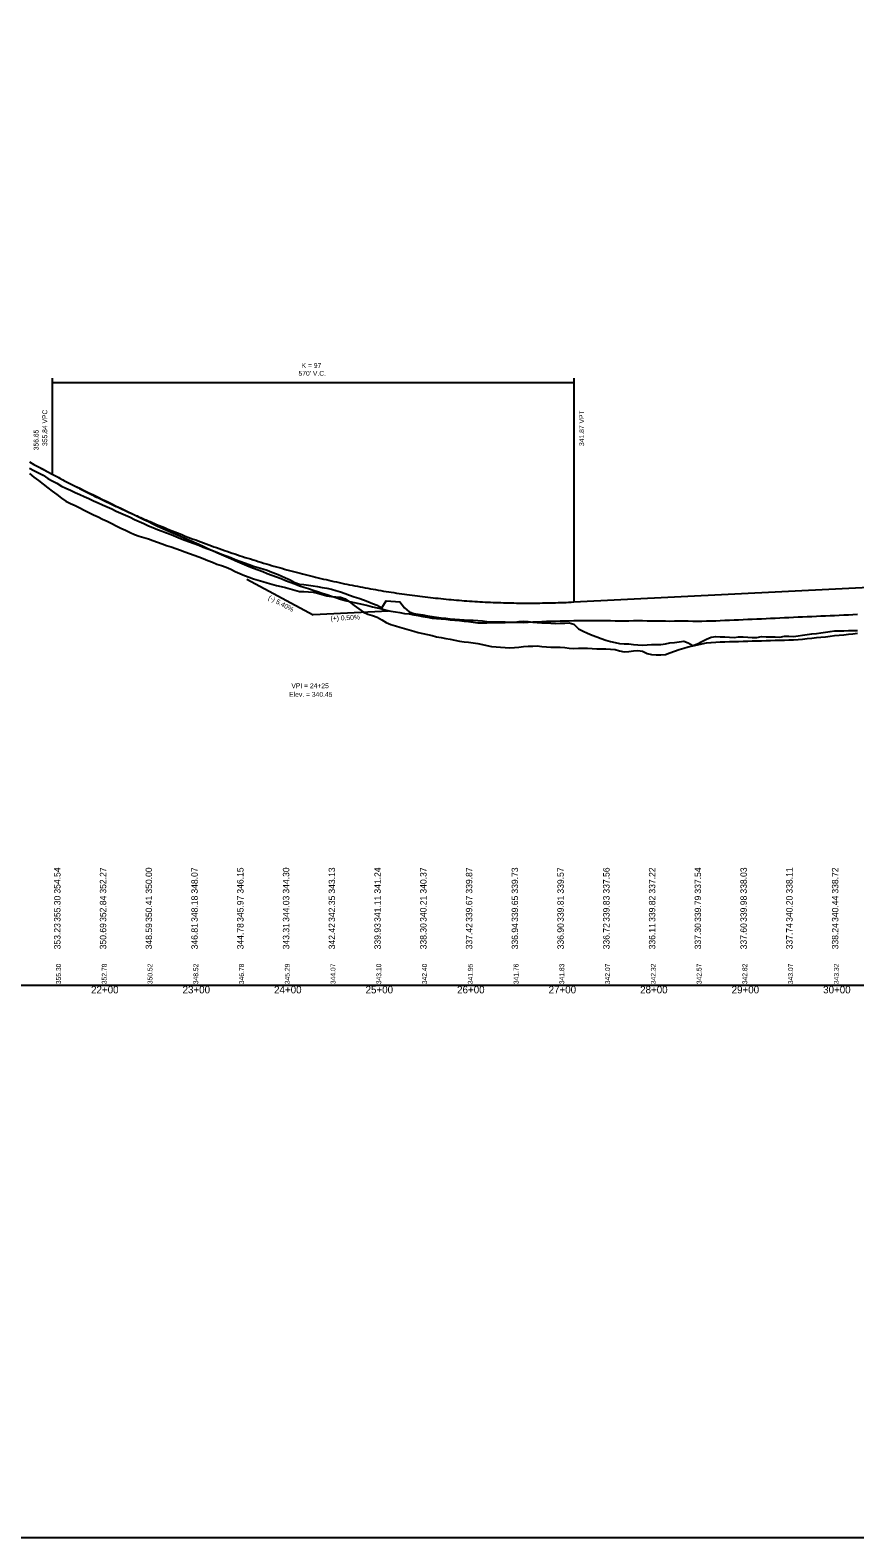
# Model space of a CAD drawing. Extents: x 2005261 to 2010661, y 1001568 to 1006764.
# Drawn here: x 2006738 to 2007639, y 1003464 to 1005112 of the extents above; entities that cross this region are included whole.
import ezdxf

# ---------------------------------------------------------------- set-up
doc = ezdxf.new("R2010")
doc.units = 0
for name, color, linetype in [('RD_DDB_GradeTX', 7, 'Continuous'), ('RD_DDB_Profile_EX', 7, 'Continuous'), ('RD_DDB_Profile_Lbl', 7, 'Continuous'), ('RD_DDB_Profile_PR', 7, 'Continuous'), ('RD_DDB_StaTX', 7, 'Continuous'), ('RD_DDB_StripGrade', 7, 'Continuous'), ('RD_DDB_VCLbl', 7, 'Continuous'), ('RD_GPK_Profile_Cell', 7, 'Continuous'), ('RD_Sketch2', 7, 'Continuous'), ('RD_Sketch3', 7, 'Continuous'), ('RD_Sketch4', 7, 'Continuous')]:
    doc.layers.add(name, color=color, linetype=linetype)

msp = doc.modelspace()

# ---------------------------------------------------------------- linework, layer by layer
at = {"layer": 'RD_DDB_GradeTX'}
for p in [(2006974.2, 1004512), (2007129, 1004477)]:
    msp.add_line(p, (2007046.7, 1004472.9), dxfattribs=at)
at = {"layer": 'RD_DDB_Profile_EX'}
for points in [[(2006736.7, 1004640.2), (2006741.7, 1004637.5), (2006746.7, 1004634.8), (2006751.7, 1004632.2), (2006756.7, 1004629.5), (2006761.7, 1004626.8), (2006766.7, 1004624.1), (2006771.7, 1004621.4), (2006776.7, 1004618.7), (2006781.7, 1004616.2), (2006786.7, 1004613.8), (2006791.7, 1004611.4), (2006796.7, 1004608.9), (2006801.7, 1004606.5), (2006806.7, 1004604.1), (2006811.7, 1004601.7), (2006816.7, 1004599.2), (2006821.7, 1004596.8), (2006826.7, 1004594.4), (2006831.7, 1004592), (2006836.7, 1004589.5), (2006841.7, 1004587.1), (2006846.7, 1004584.7), (2006851.7, 1004582.2), (2006856.7, 1004579.8), (2006861.7, 1004577.4), (2006866.7, 1004575), (2006871.7, 1004572.5), (2006876.7, 1004570.1), (2006881.7, 1004567.9), (2006886.7, 1004565.7), (2006891.7, 1004563.5), (2006896.7, 1004561.2), (2006901.7, 1004559), (2006906.7, 1004556.8), (2006911.7, 1004554.6), (2006916.7, 1004552.4), (2006921.7, 1004550.2), (2006926.7, 1004548), (2006931.7, 1004545.7), (2006936.7, 1004543.5), (2006941.7, 1004541.3), (2006946.7, 1004539.1), (2006951.7, 1004536.9), (2006956.7, 1004534.7), (2006961.7, 1004532.5), (2006966.7, 1004530.3), (2006971.7, 1004528.1), (2006976.7, 1004525.9), (2006981.7, 1004524.1), (2006986.7, 1004522.2), (2006991.7, 1004520.3), (2006996.7, 1004518.4), (2007001.7, 1004516.5), (2007006.7, 1004514.5), (2007011.7, 1004512.6), (2007016.7, 1004510.7), (2007021.7, 1004508.7), (2007026.7, 1004506.8), (2007031.7, 1004504.9), (2007036.7, 1004503.4), (2007041.7, 1004501.8), (2007046.7, 1004500.2), (2007051.7, 1004498.6), (2007056.7, 1004496.9), (2007061.7, 1004495.3), (2007066.7, 1004493.6), (2007071.7, 1004491.9), (2007076.7, 1004490.1), (2007081.7, 1004488.8), (2007086.7, 1004487.7), (2007091.7, 1004486.6), (2007096.7, 1004485.5), (2007101.7, 1004484.3), (2007106.7, 1004483.1), (2007111.7, 1004481.9), (2007116.7, 1004480.7), (2007121.7, 1004479.5), (2007126.7, 1004478.2), (2007131.7, 1004476.9), (2007136.7, 1004476.2), (2007141.7, 1004475.5), (2007146.7, 1004474.7), (2007151.7, 1004474), (2007156.7, 1004473.1), (2007161.7, 1004472.3), (2007166.7, 1004471.4), (2007171.7, 1004470.5), (2007176.7, 1004469.6)], [(2007176.7, 1004469.6), (2007181.7, 1004468.9), (2007186.7, 1004468.6), (2007191.7, 1004468.2), (2007196.7, 1004467.7), (2007201.7, 1004467.3), (2007206.7, 1004466.8), (2007211.7, 1004466.2), (2007216.7, 1004465.7), (2007221.7, 1004465.1), (2007226.7, 1004464.5), (2007231.7, 1004464.2), (2007236.7, 1004464.4), (2007241.7, 1004464.6), (2007246.7, 1004464.7), (2007251.7, 1004464.8), (2007256.7, 1004464.8), (2007261.7, 1004464.9), (2007266.7, 1004464.9), (2007271.7, 1004464.9), (2007276.7, 1004464.8), (2007281.7, 1004465), (2007286.7, 1004465.3), (2007291.7, 1004465.5), (2007296.7, 1004465.8), (2007301.7, 1004466), (2007306.7, 1004466.1), (2007311.7, 1004466.3), (2007316.7, 1004466.4), (2007321.7, 1004466.5), (2007326.7, 1004466.6), (2007331.7, 1004466.7), (2007336.7, 1004466.7), (2007341.7, 1004466.8), (2007346.7, 1004466.9), (2007351.7, 1004466.9), (2007356.7, 1004466.9), (2007361.7, 1004466.8), (2007366.7, 1004466.7), (2007371.7, 1004466.7), (2007376.7, 1004466.6), (2007381.7, 1004466.5), (2007386.7, 1004466.4), (2007391.7, 1004466.6), (2007396.7, 1004466.7), (2007401.7, 1004466.8), (2007406.7, 1004466.7), (2007411.7, 1004466.5), (2007416.7, 1004466.5), (2007421.7, 1004466.6), (2007426.7, 1004466.6), (2007431.7, 1004466.5), (2007436.7, 1004466.3), (2007441.7, 1004466.4), (2007446.7, 1004466.5), (2007451.7, 1004466.5), (2007456.7, 1004466.5), (2007461.7, 1004466.3), (2007466.7, 1004466.3), (2007471.7, 1004466.3), (2007476.7, 1004466.4), (2007481.7, 1004466.4), (2007486.7, 1004466.6), (2007491.7, 1004466.9), (2007496.7, 1004467.1), (2007501.7, 1004467.3), (2007506.7, 1004467.5), (2007511.7, 1004467.7), (2007516.7, 1004467.9), (2007521.7, 1004468.2), (2007526.7, 1004468.4), (2007531.7, 1004468.6), (2007536.7, 1004468.8), (2007541.7, 1004469.1), (2007546.7, 1004469.3), (2007551.7, 1004469.5), (2007556.7, 1004469.7), (2007561.7, 1004470), (2007566.7, 1004470.2), (2007571.7, 1004470.4), (2007576.7, 1004470.7), (2007581.7, 1004470.9), (2007586.7, 1004471.1), (2007591.7, 1004471.3), (2007596.7, 1004471.6), (2007601.7, 1004471.8), (2007606.7, 1004472), (2007611.7, 1004472.3), (2007616.7, 1004472.5), (2007621.7, 1004472.8), (2007626.7, 1004473), (2007631.7, 1004473.2), (2007636.7, 1004473.5), (2007641.7, 1004473.7)]]:
    msp.add_lwpolyline(points, dxfattribs=at)
at = {"layer": 'RD_DDB_Profile_PR'}
for p, q in [((2006746.7, 1004634.9), (2006761.7, 1004626.8)), ((2007331.7, 1004487.1), (2007916.7, 1004516.4))]:
    msp.add_line(p, q, dxfattribs=at)
msp.add_spline([(2006761.7, 1004626.8), (2006773.1, 1004620.7), (2006784.5, 1004614.7), (2006795.9, 1004608.9), (2006807.3, 1004603.2), (2006818.7, 1004597.7), (2006830.1, 1004592.3), (2006841.5, 1004587), (2006852.9, 1004581.8), (2006864.3, 1004576.8), (2006875.7, 1004571.9), (2006887.1, 1004567.2), (2006898.5, 1004562.6), (2006909.9, 1004558.1), (2006921.3, 1004553.8), (2006932.7, 1004549.6), (2006944.1, 1004545.5), (2006955.5, 1004541.5), (2006966.9, 1004537.7), (2006978.3, 1004534.1), (2006989.7, 1004530.5), (2007001.1, 1004527.1), (2007012.5, 1004523.9), (2007023.9, 1004520.7), (2007035.3, 1004517.8), (2007046.7, 1004514.9), (2007058.1, 1004512.2), (2007069.5, 1004509.6), (2007080.9, 1004507.1), (2007092.3, 1004504.8), (2007103.7, 1004502.6), (2007115.1, 1004500.6), (2007126.5, 1004498.6), (2007137.9, 1004496.9), (2007149.3, 1004495.2), (2007160.7, 1004493.7), (2007172.1, 1004492.3), (2007183.5, 1004491.1), (2007194.9, 1004489.9), (2007206.3, 1004489), (2007217.7, 1004488.1), (2007229.1, 1004487.4), (2007240.5, 1004486.8), (2007251.9, 1004486.4), (2007263.3, 1004486.1), (2007274.7, 1004485.9), (2007286.1, 1004485.9), (2007297.5, 1004486), (2007308.9, 1004486.2), (2007320.3, 1004486.6), (2007331.7, 1004487.1)], degree=3, dxfattribs=at)
at = {"layer": 'RD_DDB_VCLbl'}
for p, q in [((2006761.7, 1004731.8), (2006761.7, 1004626.8)), ((2006761.7, 1004726.8), (2007331.7, 1004726.8)), ((2007331.7, 1004731.8), (2007331.7, 1004487.1))]:
    msp.add_line(p, q, dxfattribs=at)
at = {"layer": 'RD_GPK_Profile_Cell'}
msp.add_line((2006171.7, 1004068.4), (2009471.7, 1004068.4), dxfattribs=at)
at = {"layer": 'RD_Sketch2'}
for points in [[(2006736.7, 1004627.5), (2006741.7, 1004623.6), (2006746.7, 1004619.7), (2006751.7, 1004615.8), (2006756.7, 1004611.9), (2006761.7, 1004608.3), (2006766.7, 1004604.6), (2006771.7, 1004600.7), (2006776.7, 1004597.3), (2006781.7, 1004594.9), (2006786.7, 1004592.4), (2006791.7, 1004590), (2006796.7, 1004587.5), (2006801.7, 1004585), (2006806.7, 1004582.5), (2006811.7, 1004580.1), (2006816.7, 1004577.7), (2006821.7, 1004575.3), (2006826.7, 1004572.8), (2006831.7, 1004570.4), (2006836.7, 1004567.9), (2006841.7, 1004565.5), (2006846.7, 1004563.1), (2006851.7, 1004560.8), (2006856.7, 1004559.2), (2006861.7, 1004557.6), (2006866.7, 1004556), (2006871.7, 1004554.3), (2006876.7, 1004552.5), (2006881.7, 1004550.7), (2006886.7, 1004549), (2006891.7, 1004547.2), (2006896.7, 1004545.5), (2006901.7, 1004543.8), (2006906.7, 1004541.8), (2006911.7, 1004540), (2006916.7, 1004538.2), (2006921.7, 1004536.5), (2006926.7, 1004534.7), (2006931.7, 1004532.6), (2006936.7, 1004530.5), (2006941.7, 1004528.6), (2006946.7, 1004526.8), (2006951.7, 1004525), (2006956.7, 1004522.8), (2006961.7, 1004520.6), (2006966.7, 1004518.4), (2006971.7, 1004516.2), (2006976.7, 1004514.3), (2006981.7, 1004512.4), (2006986.7, 1004511), (2006991.7, 1004509.5), (2006996.7, 1004508.1), (2007001.7, 1004506.6), (2007006.7, 1004505.2), (2007011.7, 1004504.1), (2007016.7, 1004503), (2007021.7, 1004501.5), (2007026.7, 1004499.9), (2007031.7, 1004498.5), (2007036.7, 1004498.4), (2007041.7, 1004498.3), (2007046.7, 1004497.7), (2007051.7, 1004496.9), (2007056.7, 1004495.3), (2007061.7, 1004493.9), (2007066.7, 1004493.2), (2007071.7, 1004492.6), (2007076.7, 1004492.2), (2007081.7, 1004490.4), (2007086.7, 1004487.1), (2007091.7, 1004483.3), (2007096.7, 1004479.6), (2007101.7, 1004476), (2007106.7, 1004473.7), (2007111.7, 1004472.3), (2007116.7, 1004470.6), (2007121.7, 1004467.7), (2007126.7, 1004464.8), (2007131.7, 1004462.6), (2007136.7, 1004461), (2007141.7, 1004459.5), (2007146.7, 1004458), (2007151.7, 1004456.5), (2007156.7, 1004455.1), (2007161.7, 1004453.9), (2007166.7, 1004452.7), (2007171.7, 1004451.4), (2007176.7, 1004450.3)], [(2007176.7, 1004450.3), (2007181.7, 1004449.2), (2007186.7, 1004448.2), (2007191.7, 1004447.3), (2007196.7, 1004446.4), (2007201.7, 1004445.4), (2007206.7, 1004444.4), (2007211.7, 1004443.7), (2007216.7, 1004443.1), (2007221.7, 1004442.6), (2007226.7, 1004441.7), (2007231.7, 1004440.6), (2007236.7, 1004439.6), (2007241.7, 1004438.5), (2007246.7, 1004438.1), (2007251.7, 1004437.8), (2007256.7, 1004437.5), (2007261.7, 1004437.1), (2007266.7, 1004437.2), (2007271.7, 1004437.8), (2007276.7, 1004438.4), (2007281.7, 1004438.8), (2007286.7, 1004438.9), (2007291.7, 1004439.1), (2007296.7, 1004438.6), (2007301.7, 1004438.1), (2007306.7, 1004437.8), (2007311.7, 1004437.8), (2007316.7, 1004437.8), (2007321.7, 1004437.4), (2007326.7, 1004436.7), (2007331.7, 1004436.4), (2007336.7, 1004436.6), (2007341.7, 1004436.8), (2007346.7, 1004436.7), (2007351.7, 1004436.3), (2007356.7, 1004436), (2007361.7, 1004435.9), (2007366.7, 1004435.8), (2007371.7, 1004435.6), (2007376.7, 1004435), (2007381.7, 1004433.9), (2007386.7, 1004432.5), (2007391.7, 1004433.1), (2007396.7, 1004433.6), (2007401.7, 1004434), (2007406.7, 1004433.3), (2007411.7, 1004430.9), (2007416.7, 1004429.6), (2007421.7, 1004429.5), (2007426.7, 1004429.2), (2007431.7, 1004429.8), (2007436.7, 1004431.7), (2007441.7, 1004433.5), (2007446.7, 1004435.1), (2007451.7, 1004436.7), (2007456.7, 1004438.1), (2007461.7, 1004439.3), (2007466.7, 1004440.4), (2007471.7, 1004441.4), (2007476.7, 1004442.3), (2007481.7, 1004443), (2007486.7, 1004443.2), (2007491.7, 1004443.4), (2007496.7, 1004443.6), (2007501.7, 1004443.8), (2007506.7, 1004443.8), (2007511.7, 1004444), (2007516.7, 1004444.2), (2007521.7, 1004444.4), (2007526.7, 1004444.6), (2007531.7, 1004444.6), (2007536.7, 1004444.8), (2007541.7, 1004445), (2007546.7, 1004445.1), (2007551.7, 1004445.3), (2007556.7, 1004445.3), (2007561.7, 1004445.5), (2007566.7, 1004445.7), (2007571.7, 1004445.8), (2007576.7, 1004446.1), (2007581.7, 1004446.6), (2007586.7, 1004447.2), (2007591.7, 1004447.7), (2007596.7, 1004448.3), (2007601.7, 1004448.6), (2007606.7, 1004449.2), (2007611.7, 1004449.7), (2007616.7, 1004450.3), (2007621.7, 1004450.8), (2007626.7, 1004451.2), (2007631.7, 1004451.8), (2007636.7, 1004452.4), (2007641.7, 1004453)]]:
    msp.add_lwpolyline(points, dxfattribs=at)
at = {"layer": 'RD_Sketch3'}
for points in [[(2006736.7, 1004633.2), (2006741.7, 1004630.7), (2006746.7, 1004628.1), (2006751.7, 1004625.6), (2006756.7, 1004622.1), (2006761.7, 1004619.5), (2006766.7, 1004617), (2006771.7, 1004613.8), (2006776.7, 1004611.5), (2006781.7, 1004609.2), (2006786.7, 1004606.9), (2006791.7, 1004604.6), (2006796.7, 1004602.5), (2006801.7, 1004600.1), (2006806.7, 1004597.8), (2006811.7, 1004595.5), (2006816.7, 1004593.2), (2006821.7, 1004591.1), (2006826.7, 1004588.8), (2006831.7, 1004586.5), (2006836.7, 1004584.2), (2006841.7, 1004581.9), (2006846.7, 1004579.8), (2006851.7, 1004577.4), (2006856.7, 1004575.1), (2006861.7, 1004572.8), (2006866.7, 1004570.5), (2006871.7, 1004568.4), (2006876.7, 1004566.4), (2006881.7, 1004564.5), (2006886.7, 1004562.7), (2006891.7, 1004560.8), (2006896.7, 1004558.8), (2006901.7, 1004556.6), (2006906.7, 1004554.8), (2006911.7, 1004552.9), (2006916.7, 1004551), (2006921.7, 1004549.1), (2006926.7, 1004547), (2006931.7, 1004545.1), (2006936.7, 1004543.3), (2006941.7, 1004541.4), (2006946.7, 1004539.5), (2006951.7, 1004537.4), (2006956.7, 1004535.6), (2006961.7, 1004533.7), (2006966.7, 1004531.8), (2006971.7, 1004529.9), (2006976.7, 1004527.9), (2006981.7, 1004526.4), (2006986.7, 1004524.9), (2006991.7, 1004523.4), (2006996.7, 1004521.8), (2007001.7, 1004519.6), (2007006.7, 1004517.7), (2007011.7, 1004515.7), (2007016.7, 1004513.6), (2007021.7, 1004511.4), (2007026.7, 1004508.4), (2007031.7, 1004506.7), (2007036.7, 1004506.2), (2007041.7, 1004505.6), (2007046.7, 1004504.8), (2007051.7, 1004504), (2007056.7, 1004503.1), (2007061.7, 1004502.2), (2007066.7, 1004501), (2007071.7, 1004499.7), (2007076.7, 1004498.3), (2007081.7, 1004496.4), (2007086.7, 1004494.4), (2007091.7, 1004492.8), (2007096.7, 1004491.2), (2007101.7, 1004489.4), (2007106.7, 1004487.5), (2007111.7, 1004485.6), (2007116.7, 1004483.5), (2007121.7, 1004480.8), (2007126.7, 1004488.5), (2007131.7, 1004488), (2007136.7, 1004487.5), (2007141.7, 1004487.1), (2007146.7, 1004480.7), (2007151.7, 1004476.5), (2007156.7, 1004474.6), (2007161.7, 1004473.7), (2007166.7, 1004472.9), (2007171.7, 1004472.1), (2007176.7, 1004471.1)], [(2007176.7, 1004471.1), (2007181.7, 1004470.4), (2007186.7, 1004469.8), (2007191.7, 1004469.3), (2007196.7, 1004468.8), (2007201.7, 1004468.3), (2007206.7, 1004467.9), (2007211.7, 1004467.6), (2007216.7, 1004467.3), (2007221.7, 1004467.1), (2007226.7, 1004466.9), (2007231.7, 1004466.4), (2007236.7, 1004465.8), (2007241.7, 1004465.3), (2007246.7, 1004465.3), (2007251.7, 1004465.5), (2007256.7, 1004465.3), (2007261.7, 1004465.1), (2007266.7, 1004465.1), (2007271.7, 1004465.7), (2007276.7, 1004466.3), (2007281.7, 1004465.9), (2007286.7, 1004465.1), (2007291.7, 1004464.7), (2007296.7, 1004464.5), (2007301.7, 1004464.4), (2007306.7, 1004464), (2007311.7, 1004463.7), (2007316.7, 1004463.8), (2007321.7, 1004464.1), (2007326.7, 1004464.5), (2007331.7, 1004462.8), (2007336.7, 1004457.7), (2007341.7, 1004455.3), (2007346.7, 1004453), (2007351.7, 1004451), (2007356.7, 1004449), (2007361.7, 1004447.1), (2007366.7, 1004445.4), (2007371.7, 1004444), (2007376.7, 1004442.7), (2007381.7, 1004441.7), (2007386.7, 1004441.3), (2007391.7, 1004441.2), (2007396.7, 1004440.8), (2007401.7, 1004440.2), (2007406.7, 1004439.9), (2007411.7, 1004440.2), (2007416.7, 1004440.6), (2007421.7, 1004440.6), (2007426.7, 1004440.6), (2007431.7, 1004441.4), (2007436.7, 1004442.6), (2007441.7, 1004443), (2007446.7, 1004443.6), (2007451.7, 1004444.3), (2007456.7, 1004442.6), (2007461.7, 1004439.4), (2007466.7, 1004441.5), (2007471.7, 1004443.8), (2007476.7, 1004446.3), (2007481.7, 1004448.8), (2007486.7, 1004449.5), (2007491.7, 1004449.2), (2007496.7, 1004448.9), (2007501.7, 1004448.5), (2007506.7, 1004448.2), (2007511.7, 1004449.1), (2007516.7, 1004448.9), (2007521.7, 1004448.7), (2007526.7, 1004448.4), (2007531.7, 1004448.2), (2007536.7, 1004449.4), (2007541.7, 1004449.2), (2007546.7, 1004449), (2007551.7, 1004448.9), (2007556.7, 1004448.7), (2007561.7, 1004449.7), (2007566.7, 1004449.6), (2007571.7, 1004449.5), (2007576.7, 1004450.1), (2007581.7, 1004450.8), (2007586.7, 1004451.5), (2007591.7, 1004452.2), (2007596.7, 1004452.7), (2007601.7, 1004453.4), (2007606.7, 1004454.2), (2007611.7, 1004455), (2007616.7, 1004455.5), (2007621.7, 1004455.6), (2007626.7, 1004455.7), (2007631.7, 1004455.8), (2007636.7, 1004456), (2007641.7, 1004456.1)]]:
    msp.add_lwpolyline(points, dxfattribs=at)
at = {"layer": 'RD_Sketch4'}
msp.add_lwpolyline([(2005261.5, 1006764.3), (2010661.5, 1006764.3), (2010661.5, 1003464.3), (2005261.5, 1003464.3)], close=True, dxfattribs=at)

# ---------------------------------------------------------------- texts
at = {"layer": 'RD_DDB_GradeTX'}
for s, rotation, p in [('(-) 5.40%', 331.6274, (2006997.2, 1004490.4)), ('(+) 0.50%', 2.8624, (2007065.9, 1004466.4))]:
    msp.add_text(s, height=5.33, rotation=rotation, dxfattribs=at).set_placement(p)
at = {"layer": 'RD_DDB_Profile_Lbl'}
msp.add_text('356.65', height=5.33, rotation=90, dxfattribs=at).set_placement((2006746.7, 1004652.9))
for s, p in [('Elev. = 340.45', (2007020.6, 1004383.5)), ('VPI = 24+25', (2007023, 1004392.9))]:
    msp.add_text(s, height=5.331, dxfattribs=at).set_placement(p)
at = {"layer": 'RD_DDB_StaTX'}
for s, p in [('22+00', (2006804.1, 1004059.4)), ('23+00', (2006904.1, 1004059.4)), ('24+00', (2007004.1, 1004059.4)), ('25+00', (2007104.1, 1004059.4)), ('26+00', (2007204.1, 1004059.4)), ('27+00', (2007304.1, 1004059.4)), ('28+00', (2007404.1, 1004059.4)), ('29+00', (2007504.1, 1004059.4)), ('30+00', (2007604.1, 1004059.4))]:
    msp.add_text(s, height=8, dxfattribs=at).set_placement(p)
at = {"layer": 'RD_DDB_StripGrade'}
for s, height, p in [('355.84 VPC', 5.33, (2006756.2, 1004657.6)), ('341.87 VPT', 5.33, (2007342.9, 1004657.6)), ('355.30', 7, (2006770.7, 1004137.5)), ('352.84', 7, (2006820.7, 1004137.5)), ('350.41', 7, (2006870.7, 1004137.5)), ('348.18', 7, (2006920.7, 1004137.5)), ('345.97', 7, (2006970.7, 1004137.5)), ('344.03', 7, (2007020.7, 1004137.5)), ('342.35', 7, (2007070.7, 1004137.5)), ('341.11', 7, (2007120.7, 1004137.5)), ('340.21', 7, (2007170.7, 1004137.5)), ('339.67', 7, (2007220.7, 1004137.5)), ('339.65', 7, (2007270.7, 1004137.5)), ('339.81', 7, (2007320.7, 1004137.5)), ('339.83', 7, (2007370.7, 1004137.5)), ('339.82', 7, (2007420.7, 1004137.5)), ('339.79', 7, (2007470.7, 1004137.5)), ('339.98', 7, (2007520.7, 1004137.5)), ('340.20', 7, (2007570.7, 1004137.5)), ('340.44', 7, (2007620.7, 1004137.5)), ('355.30', 5.33, (2006771.2, 1004069.4)), ('352.78', 5.33, (2006821.2, 1004069.4)), ('350.52', 5.33, (2006871.2, 1004069.4)), ('348.52', 5.33, (2006921.2, 1004069.4)), ('346.78', 5.33, (2006971.2, 1004069.4)), ('345.29', 5.33, (2007021.2, 1004069.4)), ('344.07', 5.33, (2007071.2, 1004069.4)), ('343.10', 5.33, (2007121.2, 1004069.4)), ('342.40', 5.33, (2007171.2, 1004069.4)), ('341.95', 5.33, (2007221.2, 1004069.4)), ('341.76', 5.33, (2007271.2, 1004069.4)), ('341.83', 5.33, (2007321.2, 1004069.4)), ('342.07', 5.33, (2007371.2, 1004069.4)), ('342.32', 5.33, (2007421.2, 1004069.4)), ('342.57', 5.33, (2007471.2, 1004069.4)), ('342.82', 5.33, (2007521.2, 1004069.4)), ('343.07', 5.33, (2007571.2, 1004069.4)), ('343.32', 5.33, (2007621.2, 1004069.4))]:
    msp.add_text(s, height=height, rotation=90, dxfattribs=at).set_placement(p)
at = {"layer": 'RD_DDB_VCLbl'}
for s, p in [("570' V.C.", (2007030.8, 1004734.3)), ('K = 97', (2007034.2, 1004742.9))]:
    msp.add_text(s, height=5.33, dxfattribs=at).set_placement(p)
at = {"layer": 'RD_Sketch2'}
for s, p in [('353.23', (2006770.7, 1004107.5)), ('350.69', (2006820.7, 1004107.5)), ('348.59', (2006870.7, 1004107.5)), ('346.81', (2006920.7, 1004107.5)), ('344.78', (2006970.7, 1004107.5)), ('343.31', (2007020.7, 1004107.5)), ('342.42', (2007070.7, 1004107.5)), ('339.93', (2007120.7, 1004107.5)), ('338.30', (2007170.7, 1004107.5)), ('337.42', (2007220.7, 1004107.5)), ('336.94', (2007270.7, 1004107.5)), ('336.90', (2007320.7, 1004107.5)), ('336.72', (2007370.7, 1004107.5)), ('336.11', (2007420.7, 1004107.5)), ('337.30', (2007470.7, 1004107.5)), ('337.60', (2007520.7, 1004107.5)), ('337.74', (2007570.7, 1004107.5)), ('338.24', (2007620.7, 1004107.5))]:
    msp.add_text(s, height=7, rotation=90, dxfattribs=at).set_placement(p)
at = {"layer": 'RD_Sketch3'}
for s, p in [('354.54', (2006770.7, 1004168.4)), ('352.27', (2006820.7, 1004168.4)), ('350.00', (2006870.7, 1004168.4)), ('348.07', (2006920.7, 1004168.4)), ('346.15', (2006970.7, 1004168.4)), ('344.30', (2007020.7, 1004168.4)), ('343.13', (2007070.7, 1004168.4)), ('341.24', (2007120.7, 1004168.4)), ('340.37', (2007170.7, 1004168.4)), ('339.87', (2007220.7, 1004168.4)), ('339.73', (2007270.7, 1004168.4)), ('339.57', (2007320.7, 1004168.4)), ('337.56', (2007370.7, 1004168.4)), ('337.22', (2007420.7, 1004168.4)), ('337.54', (2007470.7, 1004168.4)), ('338.03', (2007520.7, 1004168.4)), ('338.11', (2007570.7, 1004168.4)), ('338.72', (2007620.7, 1004168.4))]:
    msp.add_text(s, height=7, rotation=90, dxfattribs=at).set_placement(p)

doc.saveas('drawing.dxf')
